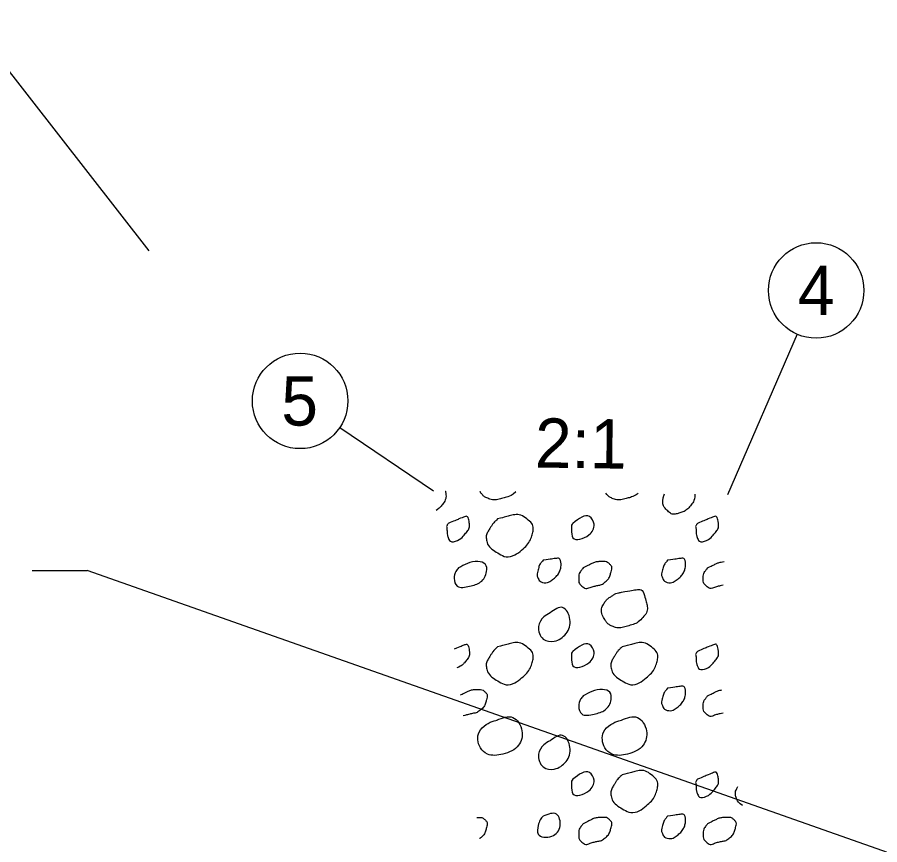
# Model space of a CAD drawing. Extents: x -1270 to 3371, y -118 to 220.
# Drawn here: x 73.78 to 98.27, y 154 to 177.48 of the extents above; entities that cross this region are included whole.
import ezdxf

# ---------------------------------------------------------------- set-up
doc = ezdxf.new("R2010")
doc.units = 0
for name, color, linetype in [('GE_P_Alignment', 7, 'Continuous'), ('GE_P_Alignment_100_Bearings', 7, 'Continuous'), ('TX_P_1', 7, 'Continuous')]:
    doc.layers.add(name, color=color, linetype=linetype)

msp = doc.modelspace()

# ---------------------------------------------------------------- linework, layer by layer
at = {"layer": 'GE_P_Alignment'}
for p, q in [((72.341, 177.485), (77.517, 170.86)), ((95.923, 168.489), (93.948, 163.936)), ((82.935, 165.84), (85.599, 164.045))]:
    msp.add_line(p, q, dxfattribs=at)
at = {"layer": 'GE_P_Alignment_100_Bearings'}
for points in [[(85.933, 164.04), (85.934, 164.036), (85.935, 164.032), (85.935, 164.028), (85.964, 163.897), (85.93, 163.75), (85.824, 163.623), (85.776, 163.566), (85.725, 163.523), (85.672, 163.49)], [(87.938, 164.014), (87.824, 163.919), (87.701, 163.874), (87.567, 163.835), (87.426, 163.793), (87.268, 163.778), (87.127, 163.837), (87.042, 163.873), (86.98, 163.935), (86.928, 164.015), (86.925, 164.019), (86.923, 164.023), (86.92, 164.028)], [(91.413, 163.969), (91.317, 163.903), (91.214, 163.867), (91.103, 163.835), (90.962, 163.793), (90.803, 163.778), (90.663, 163.837), (90.59, 163.868), (90.534, 163.917), (90.488, 163.981)], [(93.016, 163.948), (93.019, 163.839), (92.98, 163.725), (92.895, 163.623), (92.796, 163.503), (92.682, 163.447), (92.562, 163.41), (92.466, 163.381), (92.345, 163.377), (92.251, 163.47), (92.137, 163.582), (92.095, 163.714), (92.118, 163.829), (92.126, 163.869), (92.139, 163.915), (92.158, 163.959)], [(87.417, 163.246), (87.536, 163.278), (87.654, 163.309), (87.773, 163.34), (87.946, 163.385), (88.12, 163.353), (88.294, 163.208), (88.428, 163.096), (88.437, 162.93), (88.401, 162.805), (88.356, 162.649), (88.257, 162.5), (88.105, 162.37), (87.915, 162.208), (87.651, 162.145), (87.457, 162.26), (87.3, 162.353), (87.133, 162.493), (87.103, 162.658), (87.084, 162.761), (87.137, 162.881), (87.198, 162.976), (87.241, 163.045), (87.279, 163.114), (87.336, 163.169), (87.363, 163.195), (87.39, 163.221), (87.417, 163.246)], [(86.018, 163.12), (86.176, 163.185), (86.335, 163.253), (86.493, 163.313), (86.571, 163.343), (86.612, 163.169), (86.619, 163.095), (86.628, 162.995), (86.552, 162.891), (86.47, 162.792), (86.358, 162.658), (86.077, 162.56), (86.02, 162.708), (85.989, 162.786), (85.984, 162.867), (85.98, 162.948), (85.979, 162.988), (85.964, 163.033), (85.985, 163.069), (85.995, 163.087), (86.007, 163.103), (86.018, 163.12)], [(93.09, 163.12), (93.248, 163.185), (93.406, 163.253), (93.565, 163.313), (93.642, 163.343), (93.683, 163.169), (93.69, 163.095), (93.7, 162.995), (93.623, 162.891), (93.541, 162.792), (93.43, 162.658), (93.149, 162.56), (93.091, 162.708), (93.06, 162.786), (93.055, 162.867), (93.052, 162.948), (93.05, 162.988), (93.035, 163.033), (93.056, 163.069), (93.067, 163.087), (93.079, 163.103), (93.09, 163.12)], [(88.708, 162.073), (88.835, 162.092), (88.962, 162.112), (89.09, 162.129), (89.203, 162.145), (89.23, 161.899), (89.194, 161.801), (89.154, 161.692), (89.056, 161.585), (88.954, 161.507), (88.849, 161.426), (88.628, 161.44), (88.567, 161.563), (88.529, 161.641), (88.548, 161.731), (88.57, 161.809), (88.585, 161.864), (88.592, 161.927), (88.628, 161.972), (88.655, 162.006), (88.681, 162.04), (88.708, 162.073)], [(92.244, 162.073), (92.371, 162.092), (92.498, 162.112), (92.625, 162.129), (92.739, 162.145), (92.765, 161.899), (92.73, 161.801), (92.69, 161.692), (92.591, 161.585), (92.49, 161.507), (92.385, 161.426), (92.164, 161.44), (92.103, 161.563), (92.065, 161.641), (92.084, 161.731), (92.105, 161.809), (92.121, 161.864), (92.128, 161.927), (92.164, 161.972), (92.19, 162.006), (92.217, 162.04), (92.244, 162.073)], [(89.845, 161.857), (89.929, 161.899), (90.012, 161.94), (90.095, 161.982), (90.187, 162.027), (90.296, 162.036), (90.396, 162.039), (90.47, 162.041), (90.541, 162.024), (90.607, 161.958), (90.668, 161.898), (90.659, 161.818), (90.641, 161.755), (90.612, 161.65), (90.572, 161.543), (90.47, 161.458), (90.37, 161.375), (90.264, 161.363), (90.157, 161.338), (90.044, 161.312), (89.915, 161.245), (89.805, 161.344), (89.733, 161.409), (89.718, 161.486), (89.72, 161.56), (89.721, 161.626), (89.729, 161.705), (89.771, 161.76), (89.796, 161.793), (89.821, 161.825), (89.845, 161.857)], [(93.381, 161.857), (93.464, 161.899), (93.548, 161.94), (93.631, 161.982), (93.7, 162.016), (93.778, 162.029), (93.855, 162.035)], [(93.822, 161.368), (93.78, 161.356), (93.736, 161.348), (93.693, 161.338), (93.58, 161.312), (93.451, 161.245), (93.341, 161.344), (93.268, 161.409), (93.253, 161.486), (93.255, 161.56), (93.257, 161.626), (93.265, 161.705), (93.307, 161.76), (93.332, 161.793), (93.356, 161.825), (93.381, 161.857)], [(90.932, 161.167), (91.083, 161.193), (91.235, 161.222), (91.386, 161.243), (91.537, 161.264), (91.608, 161.005), (91.645, 160.863), (91.68, 160.734), (91.657, 160.577), (91.549, 160.457), (91.415, 160.309), (91.267, 160.253), (91.103, 160.204), (90.962, 160.163), (90.803, 160.147), (90.663, 160.207), (90.577, 160.243), (90.515, 160.305), (90.464, 160.385), (90.377, 160.519), (90.352, 160.704), (90.427, 160.83), (90.477, 160.914), (90.545, 160.988), (90.632, 161.043), (90.706, 161.09), (90.776, 161.134), (90.858, 161.152), (90.885, 161.157), (90.913, 161.163), (90.94, 161.169)], [(86.192, 159.561), (86.292, 159.603), (86.393, 159.644), (86.493, 159.682), (86.571, 159.712), (86.612, 159.539), (86.619, 159.464), (86.628, 159.365), (86.552, 159.26), (86.47, 159.162), (86.422, 159.104), (86.342, 159.053), (86.263, 159.025)], [(87.417, 159.616), (87.536, 159.647), (87.654, 159.678), (87.773, 159.709), (87.946, 159.754), (88.12, 159.722), (88.294, 159.577), (88.428, 159.465), (88.437, 159.299), (88.401, 159.175), (88.356, 159.018), (88.257, 158.87), (88.105, 158.74), (87.915, 158.578), (87.651, 158.514), (87.457, 158.629), (87.3, 158.722), (87.133, 158.862), (87.103, 159.027), (87.084, 159.13), (87.137, 159.25), (87.198, 159.346), (87.241, 159.414), (87.279, 159.483), (87.336, 159.538), (87.363, 159.564), (87.39, 159.59), (87.417, 159.616)], [(90.953, 159.616), (91.071, 159.647), (91.19, 159.678), (91.309, 159.709), (91.482, 159.754), (91.656, 159.722), (91.83, 159.577), (91.964, 159.465), (91.973, 159.299), (91.937, 159.175), (91.892, 159.018), (91.793, 158.87), (91.641, 158.74), (91.451, 158.578), (91.187, 158.514), (90.993, 158.629), (90.835, 158.722), (90.669, 158.862), (90.639, 159.027), (90.62, 159.13), (90.673, 159.25), (90.734, 159.346), (90.777, 159.414), (90.815, 159.483), (90.872, 159.538), (90.899, 159.564), (90.926, 159.59), (90.953, 159.616)], [(93.09, 159.49), (93.248, 159.554), (93.406, 159.622), (93.565, 159.682), (93.642, 159.712), (93.683, 159.539), (93.69, 159.464), (93.7, 159.365), (93.623, 159.26), (93.541, 159.162), (93.43, 159.028), (93.149, 158.93), (93.091, 159.077), (93.06, 159.156), (93.055, 159.237), (93.052, 159.317), (93.05, 159.358), (93.035, 159.402), (93.056, 159.438), (93.067, 159.457), (93.079, 159.473), (93.09, 159.49)], [(92.244, 158.443), (92.371, 158.461), (92.498, 158.481), (92.625, 158.499), (92.739, 158.514), (92.765, 158.269), (92.73, 158.17), (92.69, 158.062), (92.591, 157.954), (92.49, 157.876), (92.385, 157.796), (92.164, 157.809), (92.103, 157.933), (92.065, 158.011), (92.084, 158.101), (92.105, 158.179), (92.121, 158.234), (92.128, 158.297), (92.164, 158.342), (92.19, 158.376), (92.217, 158.409), (92.244, 158.443)], [(86.365, 158.254), (86.43, 158.286), (86.495, 158.319), (86.56, 158.351), (86.651, 158.397), (86.761, 158.406), (86.86, 158.409), (86.934, 158.411), (87.005, 158.394), (87.071, 158.328), (87.132, 158.268), (87.123, 158.188), (87.105, 158.125), (87.076, 158.02), (87.037, 157.913), (86.935, 157.828), (86.835, 157.745), (86.729, 157.733), (86.621, 157.708), (86.564, 157.695), (86.504, 157.671), (86.443, 157.664)], [(93.819, 157.737), (93.778, 157.726), (93.735, 157.718), (93.693, 157.708), (93.58, 157.682), (93.451, 157.615), (93.341, 157.714), (93.268, 157.779), (93.253, 157.855), (93.255, 157.93), (93.257, 157.996), (93.265, 158.074), (93.307, 158.13), (93.332, 158.162), (93.356, 158.194), (93.381, 158.226)], [(93.381, 158.226), (93.464, 158.268), (93.548, 158.31), (93.631, 158.351), (93.68, 158.375), (93.733, 158.389), (93.788, 158.397)], [(90.953, 155.985), (91.071, 156.017), (91.19, 156.048), (91.309, 156.079), (91.482, 156.124), (91.656, 156.092), (91.83, 155.947), (91.964, 155.835), (91.973, 155.669), (91.937, 155.545), (91.892, 155.388), (91.793, 155.239), (91.641, 155.11), (91.451, 154.947), (91.187, 154.884), (90.993, 154.999), (90.835, 155.092), (90.669, 155.232), (90.639, 155.397), (90.62, 155.5), (90.673, 155.62), (90.734, 155.715), (90.777, 155.784), (90.815, 155.853), (90.872, 155.908), (90.899, 155.934), (90.926, 155.96), (90.953, 155.985)], [(93.09, 155.86), (93.248, 155.924), (93.406, 155.992), (93.565, 156.052), (93.642, 156.082), (93.683, 155.908), (93.69, 155.834), (93.7, 155.734), (93.623, 155.63), (93.541, 155.531), (93.43, 155.397), (93.149, 155.299), (93.091, 155.447), (93.06, 155.525), (93.055, 155.606), (93.052, 155.687), (93.05, 155.727), (93.035, 155.772), (93.056, 155.808), (93.067, 155.826), (93.079, 155.842), (93.09, 155.86)], [(94.367, 155.112), (94.272, 155.192), (94.194, 155.289), (94.175, 155.397), (94.159, 155.479), (94.19, 155.572), (94.234, 155.654)], [(86.825, 154.777), (86.837, 154.777), (86.849, 154.778), (86.86, 154.778), (86.934, 154.78), (87.005, 154.763), (87.071, 154.697), (87.132, 154.637), (87.123, 154.557), (87.105, 154.494), (87.076, 154.389), (87.037, 154.282), (86.935, 154.197), (86.925, 154.189), (86.915, 154.182), (86.904, 154.175)], [(89.845, 154.596), (89.929, 154.638), (90.012, 154.679), (90.095, 154.721), (90.187, 154.766), (90.296, 154.775), (90.396, 154.778), (90.47, 154.78), (90.541, 154.763), (90.607, 154.697), (90.668, 154.637), (90.659, 154.557), (90.641, 154.494), (90.612, 154.389), (90.572, 154.282), (90.47, 154.197), (90.37, 154.114), (90.264, 154.102), (90.157, 154.077), (90.044, 154.051), (89.915, 153.984), (89.805, 154.083), (89.733, 154.148), (89.718, 154.225), (89.72, 154.299), (89.721, 154.365), (89.729, 154.444), (89.771, 154.499), (89.796, 154.532), (89.821, 154.564), (89.845, 154.596)], [(92.244, 154.812), (92.371, 154.831), (92.498, 154.851), (92.625, 154.868), (92.739, 154.884), (92.765, 154.638), (92.73, 154.54), (92.69, 154.432), (92.591, 154.324), (92.49, 154.246), (92.385, 154.165), (92.164, 154.179), (92.103, 154.302), (92.065, 154.38), (92.084, 154.47), (92.105, 154.548), (92.121, 154.603), (92.128, 154.666), (92.164, 154.712), (92.19, 154.745), (92.217, 154.779), (92.244, 154.812)], [(93.381, 154.596), (93.464, 154.638), (93.548, 154.679), (93.631, 154.721), (93.723, 154.766), (93.832, 154.775), (93.932, 154.778), (94.006, 154.78), (94.077, 154.763), (94.143, 154.697), (94.203, 154.637), (94.195, 154.557), (94.177, 154.494), (94.148, 154.389), (94.108, 154.282), (94.006, 154.197), (93.906, 154.114), (93.8, 154.102), (93.693, 154.077), (93.58, 154.051), (93.451, 153.984), (93.341, 154.083), (93.268, 154.148), (93.253, 154.225), (93.255, 154.299), (93.257, 154.365), (93.265, 154.444), (93.307, 154.499), (93.332, 154.532), (93.356, 154.564), (93.381, 154.596)]]:
    msp.add_open_spline(points, degree=3, dxfattribs=at)
for points in [[(89.554, 163.12), (90.029, 163.313), (90.155, 163.095), (90.005, 162.792), (89.555, 162.708), (89.516, 162.948), (89.52, 163.069), (89.554, 163.12)], [(86.31, 161.857), (86.56, 161.982), (86.86, 162.039), (87.071, 161.958), (87.105, 161.755), (86.935, 161.458), (86.621, 161.338), (86.27, 161.344), (86.184, 161.56), (86.235, 161.76), (86.31, 161.857)], [(88.912, 160.585), (89.264, 160.736), (89.471, 160.397), (89.36, 159.992), (89.026, 159.78), (88.715, 159.839), (88.582, 160.198), (88.728, 160.466), (88.912, 160.585)], [(89.554, 159.49), (90.029, 159.682), (90.155, 159.464), (90.005, 159.162), (89.555, 159.077), (89.516, 159.317), (89.52, 159.438), (89.554, 159.49)], [(89.845, 158.226), (90.095, 158.351), (90.396, 158.409), (90.607, 158.328), (90.641, 158.125), (90.47, 157.828), (90.157, 157.708), (89.805, 157.714), (89.72, 157.93), (89.771, 158.13), (89.845, 158.226)], [(87.396, 157.537), (87.85, 157.613), (88.11, 157.233), (88.013, 156.826), (87.567, 156.574), (87.127, 156.576), (86.928, 156.755), (86.891, 157.2), (87.096, 157.413), (87.322, 157.521), (87.405, 157.539)], [(90.932, 157.537), (91.386, 157.613), (91.645, 157.233), (91.549, 156.826), (91.103, 156.574), (90.663, 156.576), (90.464, 156.755), (90.427, 157.2), (90.632, 157.413), (90.858, 157.521), (90.94, 157.539)], [(88.912, 156.955), (89.264, 157.105), (89.471, 156.767), (89.36, 156.362), (89.026, 156.15), (88.715, 156.209), (88.582, 156.568), (88.728, 156.835), (88.912, 156.955)], [(89.554, 155.86), (90.029, 156.052), (90.155, 155.834), (90.005, 155.531), (89.555, 155.447), (89.516, 155.687), (89.52, 155.808), (89.554, 155.86)], [(88.708, 154.812), (89.09, 154.868), (89.194, 154.54), (88.954, 154.246), (88.567, 154.302), (88.57, 154.548), (88.628, 154.712), (88.708, 154.812)]]:
    msp.add_spline(points, degree=3, dxfattribs=at)
at = {"layer": 'TX_P_1'}
for p in [(74.201, 161.784), (106.483, 150.963)]:
    msp.add_line(p, (75.765, 161.784), dxfattribs=at)
for centre in [(96.462, 169.732), (81.811, 166.597)]:
    msp.add_circle(centre, 1.355, dxfattribs=at)

# ---------------------------------------------------------------- texts
for s, p in [('4', (95.944, 169.032)), ('5', (81.276, 165.897))]:
    msp.add_text(s, height=1.4, dxfattribs=at).set_placement(p)
msp.add_text('2:1', height=1.4, rotation=359.25, dxfattribs=at).set_placement((88.471, 164.707))

doc.saveas('drawing.dxf')
